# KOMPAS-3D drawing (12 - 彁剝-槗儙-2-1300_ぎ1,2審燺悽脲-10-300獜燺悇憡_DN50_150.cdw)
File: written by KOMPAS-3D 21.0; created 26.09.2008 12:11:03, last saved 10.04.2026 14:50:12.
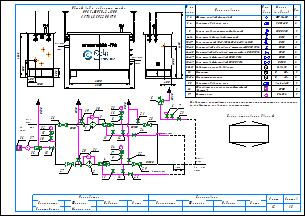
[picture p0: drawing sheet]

Sheets 1-2: A3, landscape

Document properties: Наименование: Макро:21; Автор: RaskoAdmin; Форматы листов документа: 2xA3; Полное имя файла: \\UR38nt01\Departments\КТО\КБ ПУРДГ\Заявки\Прайс-лист на типовые шкафы ГРПШ\ПРДГ_стандарт_20_03_2026\ПРДГ с РДСК\ПРДГ-ШУГО-2-1300_до1,2МПа_Рвых-10-300кПа_РДСК_DN50_150.cdw

Title block, sheet 1: Наименование: Пункт учета газа / ПУГ-Ш-400-Р / ЛГТИ.485922.001ТУ; designation: ЛГТИ.03.4411141; sheet number: 1; Количество листов документа: 2; organisation: ООО "ЭЛЬСТЕР Газэлектроника"; Форматы листов документа: A3; stored path: C:\Рабочие документы\Компас\ПУГ\Схема.cdw; Разработал: Устинов; Проверил: Кошкин; Утвердил: Кошкин
Title block, sheet 2: sheet number: 2; stored path: D:\Рабочие документы\Заявки\ПУРДГ\ПУРДГ-ШУЭО-2-100-Р 4411220.cdw; designation, second copy: ЛГТИ.03.4411141-

Views: Вид 1, Вид 2
Referenced files: wcvoit.frw
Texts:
  Normal
  Вход
  газа
  PDI
  Выход
  Р=     кПа
  DN150
  DN50
  DN20
  Импульс DN20
  ≥5DN
  HYSWLongFangSong
  № на
  схеме
  Усл.
  обозн.
  Марка
  (модель)
  Кол.
  Фильтр газовый фланцевый
  ФГ 16-50
  Регулятор давления газа
  РДCК-50
  Клапан предохранительный сбросной
  КПС DN20
  Кран шаровой газовый латунный
  DN15
  Кран кнопочный VE-РАСКО-НЗ-1,6-G1/2-М20
  Кран шаровой "под приварку" штуцерный DN20 PN16
  Кран шаровой "под приварку" штуцерный п/п DN20 PN16
  Кран шаровой фланцевый DN50 PN16
  Кран шаровой фланцевый DN150 PN16
  Индикатор перепада давления
  Delta 15
  Манометр
  Манометр-напоромер
  0...     МПа
  0...     кПа
  Обогреватель газогорелочный шкафной
  (Эльтон")
  Счетчик газа
  Venio-A-15
  ОГШН
  BK-G1,6
  Общий вид и габариты шкафа
  ПРДГ-ШУГО-2-1300
  Выход газа
  Вход газа
  Схема открывания дверей
  Р=        МПа
  logo-rasko-ge.png
  Предприятие изготовитель может заменять комплектующие на аналогичные,
  не ухудшающие заявленных характеристик.
  Должность
  Конструктор
  Фамилия
  Подпись
  Дата
  Согласовано
  Максимкин
  Лист
  Листов
  POLYLINE_STYLE_0.18_RGB_0_0_0
  POLYLINE_STYLE_0.50_RGB_0_0_0
  POLYLINE_STYLE_0.34_RGB_0_0_0
  PHANTOM_RGB_0_0_0_SC_1_THICK_0.18
  K5LT_THIN_RGB_0_0_0_THICK_0.18
  K5LT32769_RGB_0_0_0_THICK_0.18
  K5LT12_RGB_0_0_0_SC_1_THICK_0.18
  K5LT_DASHED_RGB_0_0_0_SC_1_THICK_0.18
  ACISOTGL_RGB_0_0_0_SC_0.8_THICK_0.25
  CONTINUOUS_RGB_0_127_31_THICK_0.3
  CONTINUOUS_RGB_0_0_255_THICK_0.35
  CONTINUOUS_RGB_255_0_0_THICK_0.35
  POLYLINE_STYLE_0.25_RGB_0_0_0
  CONTINUOUS_RGB_0_0_0_THICK_0.5
  POLYLINE_STYLE_0.35_RGB_0_0_255
  CONTINUOUS_RGB_0_0_0_THICK_0.4
  CONTINUOUS_RGB_0_0_0_THICK_0.35
  Без оформления
Dimensions and other numbers on the sheet: 1; 2; 3; 4; 5; 10; 27; 28; 29; 23; 8; 12; 18; 19; 20; 21; 22; 25; 24; 30; 31; 15; 16; 35; 36; 26; 6; 7; 11; 14; 13; 33; 1, 2; 3, 4; 6-14; 9; 15-17; 18-23; 24-25; 26-27; 28-29; 30-31; 32; 33-34; 37; 400; 1050; 500; 305; 2500; 1565; 2800; 17; 34; 1000; 4130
